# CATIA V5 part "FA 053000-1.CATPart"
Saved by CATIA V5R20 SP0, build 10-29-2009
Part number: FA 053000-1
Revision: ANY
Definition: UNKNOWN
Nomenclature: FA 053000-1
Source: Unknown
Bounding box of the stored display mesh (mm): x -1.9 to 1.9, y -1.1 to 2.45, z -1.9 to 1.9
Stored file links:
  C:\Users\Utente\Desktop\IO LAVORO\3D X SITO CF\CUMSA\3D files FA\FA 0530SF\FA 053000-1.CATPart

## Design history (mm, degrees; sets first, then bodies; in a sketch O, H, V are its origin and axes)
Body1 "Cortar-Extruir1" (main body)
  Solid1: solid without history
